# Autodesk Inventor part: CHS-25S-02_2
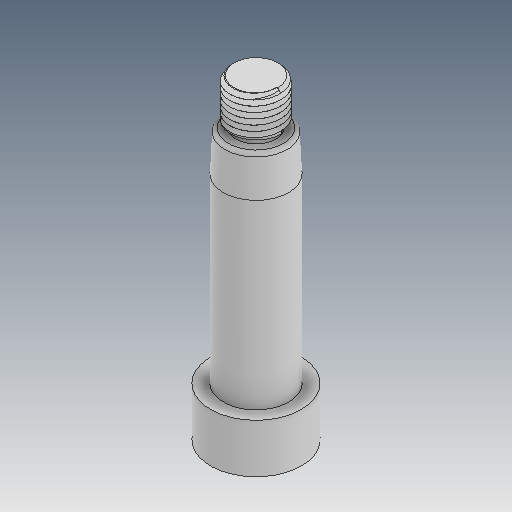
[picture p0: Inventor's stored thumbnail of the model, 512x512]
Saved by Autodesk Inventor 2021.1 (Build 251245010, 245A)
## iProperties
Created: 2019-05
Part Number: CHS-25S-02_2
Material: Ogólny
Document SubType Name: Modeling
Designer: user
Density: 1 g/cm^3
Appearance: Domyślna
Author: user
Revision Number: ÈÎºÎ
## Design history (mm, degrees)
feature "ÊäÈë1"
feature "ÊäÈë2"
node "Bryła1"
node "Bryła2"
